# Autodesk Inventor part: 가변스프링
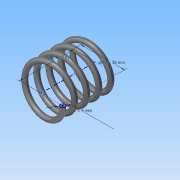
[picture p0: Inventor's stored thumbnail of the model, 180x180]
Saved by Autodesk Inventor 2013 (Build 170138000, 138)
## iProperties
Created: 2015-04
Part Number: 가변스프링
Material: 강철, 탄소
Document SubType Name: Modeling
Designer: Administrator
Density: 7.87 g/cm^3
Mass: 47.9935 g
Surface Area: 62.0176 cm^2
Volume: 6.09829 cm^3
Author: Administrator
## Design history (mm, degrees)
sketch "스케치1"
  geometry: L1 (0, 0)-(17.5, 0); L2 (17.5, 0)-(17.5, 43.5); L3 (17.5, 43.5)-(0, 43.5); L4 (0, 43.5)-(0, 0); C1 r 2 at (17.5, 0)
  constraints: 8 end point, 2 parallel, 1 centre point, 1 coincident, 1 horizontal, 1 perpendicular
  dimensions: "d0" = 43.5 distance of L3.end L1.start (derived); "d1" = 35 diameter of L2 L4; "d2" = 4 diameter of C1
feature "코일1" sketch "스케치1" pitch "d3" = 10; turns "d5" = 4.5; dims "d4" = 43.5 (= d0), "d6" = 0, angle "d7" = 90 deg, angle "d8" = 90 deg, "d9" = 0, "d10" = 0
sketch "스케치2"
  geometry: L1 (-19.5, 0)-(-15.5, 0) reference; 1 further point
  constraints: 1 horizontal alignment
extrude "돌출1" cut sketch "스케치2" distance "d11" = 10; taper "d12" = 0 deg
node "작업 평면1"
sketch "스케치3"
  geometry: L1 (15.5, 0)-(19.5, 0) reference; 1 further point
  constraints: 1 horizontal alignment
extrude "돌출2" cut sketch "스케치3" distance "d14" = 10; taper "d15" = 0 deg
node "솔리드1"
node "절단 모서리 투영1"
node "절단 모서리 투영2"
other parameters: "d13" = 43.5 (= d0)
